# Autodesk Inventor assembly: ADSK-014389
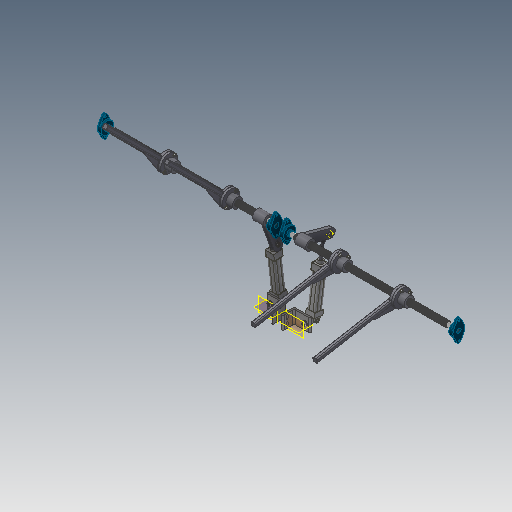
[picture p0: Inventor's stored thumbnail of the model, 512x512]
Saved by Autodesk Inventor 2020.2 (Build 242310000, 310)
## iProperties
Created: 2019-10
Part Number: ADSK-014389
Document SubType Name: Assembly
Designer: lutzd
Mass: 33938.9 g
Surface Area: 13738.5 cm^2
Volume: 4624.84 cm^3
Density: 7.3384 g/cm^3
VLDS_Profile: Default Assembly
VLDS_TimeStamp: 2016-07-29
VLDS_FailCnt: 0
VLDS_AcceptCnt: 0
Dimensions: 670,2x834,4x2050 mm
Mass: 33,939 kg
DocNumber: ADSK-014389
Folder: 01 - Themengebiete\Simplification\01 - Packaging machine\
VDS_Category: 3D Komponenten
VDS_NumSchm: Autodesk
Title: SUB-219310
Author: lutzd
Revision Number: -
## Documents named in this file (17)
- D:\07 - DEMODATEN\OTX 2019 - Dataset - UPDATE - Dez2019\Designs\07-Packing machine\ADSK-014389.iam
- D:\07 - DEMODATEN\OTX 2019 - Dataset - UPDATE - Dez2019\Designs\07-Packing machine\Parts\ADSK-011712.ipt
- D:\07 - DEMODATEN\OTX 2019 - Dataset - UPDATE - Dez2019\Designs\07-Packing machine\Parts\ADSK-011475.ipt
- D:\07 - DEMODATEN\OTX 2019 - Dataset - UPDATE - Dez2019\Designs\07-Packing machine\500598.iam
- D:\07 - DEMODATEN\OTX 2019 - Dataset - UPDATE - Dez2019\Designs\07-Packing machine\500600.iam
- D:\07 - DEMODATEN\OTX 2019 - Dataset - UPDATE - Dez2019\Content Center Files\de-DE\DIN 125-1  B\DIN 125-1 - B 8,4.ipt
- D:\07 - DEMODATEN\OTX 2019 - Dataset - UPDATE - Dez2019\Content Center Files\de-DE\ISO 4762(2)\ISO 4762 - M8 x 25ISO.ipt
- D:\07 - DEMODATEN\OTX 2019 - Dataset - UPDATE - Dez2019\Designs\07-Packing machine\500599.iam
- D:\07 - DEMODATEN\OTX 2019 - Dataset - UPDATE - Dez2019\Designs\07-Packing machine\Parts\ISO 657-2 - 100x 75x10-75.ipt
- D:\07 - DEMODATEN\OTX 2019 - Dataset - UPDATE - Dez2019\Designs\07-Packing machine\Parts\ADSK-011764.ipt
- D:\07 - DEMODATEN\OTX 2019 - Dataset - UPDATE - Dez2019\Designs\07-Packing machine\A105156.iam
- D:\07 - DEMODATEN\OTX 2019 - Dataset - UPDATE - Dez2019\Designs\07-Packing machine\A081742.iam
- D:\07 - DEMODATEN\OTX 2019 - Dataset - UPDATE - Dez2019\Content Center Files\de-DE\DIN 125-1  B\DIN 125-1 - B 10,5.ipt
- D:\07 - DEMODATEN\OTX 2019 - Dataset - UPDATE - Dez2019\Content Center Files\de-DE\ISO 4032(1)\ISO 4032 - M10DIN EN.ipt
- D:\07 - DEMODATEN\OTX 2019 - Dataset - UPDATE - Dez2019\Content Center Files\de-DE\ISO 4762(2)\ISO 4762 - M10 x 50ISO.ipt
- D:\07 - DEMODATEN\OTX 2019 - Dataset - UPDATE - Dez2019\Content Center Files\de-DE\DIN 125-1  B\DIN 125-1 - B 13.ipt
- D:\07 - DEMODATEN\OTX 2019 - Dataset - UPDATE - Dez2019\Content Center Files\de-DE\ISO 4762(2)\ISO 4762 - M12 x 25ISO.ipt
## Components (60 placed, 16 different names)
1. ADSK-011712:1 — Fluchtend:1, Passend:1, Passend:2, Passend:7, Fluchtend:10, Fluchtend:91, Fluchtend:89
2. ADSK-011712:2 — Passend:3, Passend:4, Passend:5, Passend:6, Fluchtend:8, Fluchtend:13, Fluchtend:88, Passend:90
3. ADSK-011712:3 — Passend:6, Passend:9, Passend:10, Passend:14
4. ADSK-011712:4 — Passend:7, Passend:8, Passend:11, Fluchtend:2, Fluchtend:6
5. ADSK-011475:1 — Passend:13, Fluchtend:2, Passend:16
6. ADSK-011475:2 — Passend:12, Passend:14, Passend:80, Winkel:1, Passend:83
7. 500598:1 [sub-assembly] — Passend:15, Passend:16, Passend:18, Passend:19, Passend:21, Passend:23, Passend:25, Fluchtend:3
8. 500600:1 [sub-assembly] — Passend:17, Passend:18, Passend:19, Fluchtend:6, Fluchtend:7
9. 500598:2 [sub-assembly] — Passend:46, Passend:77, Fluchtend:3, Winkel:2
10. 500600:2 [sub-assembly] — Passend:46, Fluchtend:7, Winkel:3
11. 500598:3 [sub-assembly] — Passend:78, Passend:83
12. 500600:3 [sub-assembly] — Fluchtend:8, Fluchtend:9, Winkel:4
13. 500598:4 [sub-assembly] — Passend:79, Passend:80
14. 500600:4 [sub-assembly] — Fluchtend:9
15. 500599:1 [sub-assembly] — Passend:81, Winkel:1, Passend:96, Passend:100, Passend:102, Passend:104
16. 500599:2 [sub-assembly] — Passend:82, Winkel:2, Passend:98, Passend:99, Passend:106
17. ISO 657-2 - 100x 75x10-75:1 — Fluchtend:10, Fluchtend:91, Einfügen:2, Fluchtend:90, Fluchtend:89, Fluchtend:92
18. ISO 657-2 - 100x 75x10-75:2 — Fluchtend:13, Fluchtend:88, Einfügen:1, Fluchtend:87, Passend:90, Fluchtend:92
19. ADSK-011764:1 — Einfügen:1, Fluchtend:87, Passend:91, Passend:95
20. ADSK-011764:2 — Einfügen:2, Fluchtend:90, Passend:92, Passend:94
21. A105156:1 [sub-assembly] — Passend:92, Einfügen:3, Passend:94, Passend:97
22. A105156:2 [sub-assembly] — Passend:91, Einfügen:4, Passend:95, Passend:101
23. A081742:1 [sub-assembly] — Einfügen:4, Passend:96, Passend:100, Passend:101, Passend:102
24. A081742:2 [sub-assembly] — Einfügen:3, Passend:97, Passend:98, Passend:99
25. DIN 125-1 B B 10,5:1
26. DIN 125-1 B B 10,5:2 — Passend:104
27. DIN 125-1 B B 10,5:3
28. DIN 125-1 B B 10,5:4 — Passend:106
29. DIN EN 24032 M10:1
30. DIN EN 24032 M10:2
31. ISO 4762 M10 x 50:1
32. ISO 4762 M10 x 50:2
33. DIN 125-1 B B 13:1
34. DIN 125-1 B B 13:2
35. ISO 4762 M12 x 25:1
36. ISO 4762 M12 x 25:2
37. DIN 125-1 B B 8,4:1 — Passend:21, Passend:27, Passend:29, Passend:31
38. DIN 125-1 B B 8,4:2 — Passend:23
39. DIN 125-1 B B 8,4:3 — Passend:25
40. ISO 4762 M8 x 25:1 — Passend:27
41. ISO 4762 M8 x 25:2 — Passend:29
42. ISO 4762 M8 x 25:3 — Passend:31
43. DIN 125-1 B B 8,4:4
44. DIN 125-1 B B 8,4:5
45. DIN 125-1 B B 8,4:6
46. ISO 4762 M8 x 25:4
47. ISO 4762 M8 x 25:5
48. ISO 4762 M8 x 25:6
49. DIN 125-1 B B 8,4:7
50. DIN 125-1 B B 8,4:8
51. DIN 125-1 B B 8,4:9
52. ISO 4762 M8 x 25:7
53. ISO 4762 M8 x 25:8
54. ISO 4762 M8 x 25:9
55. DIN 125-1 B B 8,4:10
56. DIN 125-1 B B 8,4:11
57. DIN 125-1 B B 8,4:12
58. ISO 4762 M8 x 25:10
59. ISO 4762 M8 x 25:11
60. ISO 4762 M8 x 25:12
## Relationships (70: Mate 47, Flush 15, Angle 4, Insert 4)
- Winkel:3 [Angle]: 500600:2
- Winkel:4 [Angle]: 500600:3
- Fluchtend:1 [Flush]: ADSK-011712:1
- Passend:1 [Mate]: ADSK-011712:1
- Passend:2 [Mate]: ADSK-011712:1
- Passend:3 [Mate]: ADSK-011712:2
- Passend:4 [Mate]: ADSK-011712:2
- Passend:5 [Mate]: ADSK-011712:2
- Passend:6 [Mate]: ADSK-011712:2 ↔ ADSK-011712:3
- Passend:7 [Mate]: ADSK-011712:1 ↔ ADSK-011712:4
- Passend:8 [Mate]: ADSK-011712:4
- Passend:9 [Mate]: ADSK-011712:3
- Passend:10 [Mate]: ADSK-011712:3
- Passend:11 [Mate]: ADSK-011712:4
- Passend:12 [Mate]: ADSK-011475:2
- Passend:13 [Mate]: ADSK-011475:1
- Passend:14 [Mate]: ADSK-011712:3 ↔ ADSK-011475:2
- Fluchtend:2 [Flush]: ADSK-011712:4 ↔ ADSK-011475:1
- Passend:15 [Mate]: 500598:1
- Passend:16 [Mate]: ADSK-011475:1 ↔ 500598:1
- Passend:17 [Mate]: 500600:1
- Passend:18 [Mate]: 500598:1 ↔ 500600:1
- Passend:19 [Mate]: 500598:1 ↔ 500600:1
- Passend:21 [Mate]: 500598:1 ↔ DIN 125-1 B B 8,4:1
- Passend:23 [Mate]: 500598:1 ↔ DIN 125-1 B B 8,4:2
- Passend:25 [Mate]: 500598:1 ↔ DIN 125-1 B B 8,4:3
- Passend:27 [Mate]: DIN 125-1 B B 8,4:1 ↔ ISO 4762 M8 x 25:1
- Passend:29 [Mate]: DIN 125-1 B B 8,4:1 ↔ ISO 4762 M8 x 25:2
- Passend:31 [Mate]: DIN 125-1 B B 8,4:1 ↔ ISO 4762 M8 x 25:3
- Passend:46 [Mate]: 500598:2 ↔ 500600:2
- Passend:77 [Mate]: 500598:2
- Passend:78 [Mate]: 500598:3
- Passend:79 [Mate]: 500598:4
- Fluchtend:3 [Flush]: 500598:1 ↔ 500598:2
- Fluchtend:6 [Flush]: ADSK-011712:4 ↔ 500600:1
- Fluchtend:7 [Flush]: 500600:1 ↔ 500600:2
- Fluchtend:8 [Flush]: ADSK-011712:2 ↔ 500600:3
- Fluchtend:9 [Flush]: 500600:3 ↔ 500600:4
- Passend:80 [Mate]: ADSK-011475:2 ↔ 500598:4
- Passend:81 [Mate]: 500599:1
- Passend:82 [Mate]: 500599:2
- Winkel:1 [Angle]: ADSK-011475:2 ↔ 500599:1
- Passend:83 [Mate]: ADSK-011475:2 ↔ 500598:3
- Winkel:2 [Angle]: 500598:2 ↔ 500599:2
- Fluchtend:10 [Flush]: ADSK-011712:1 ↔ ISO 657-2 - 100x 75x10-75:1
- Fluchtend:91 [Flush]: ADSK-011712:1 ↔ ISO 657-2 - 100x 75x10-75:1
- Fluchtend:13 [Flush]: ADSK-011712:2 ↔ ISO 657-2 - 100x 75x10-75:2
- Fluchtend:88 [Flush]: ADSK-011712:2 ↔ ISO 657-2 - 100x 75x10-75:2
- Einfügen:1 [Insert]: ISO 657-2 - 100x 75x10-75:2 ↔ ADSK-011764:1
- Einfügen:2 [Insert]: ISO 657-2 - 100x 75x10-75:1 ↔ ADSK-011764:2
- Fluchtend:87 [Flush]: ISO 657-2 - 100x 75x10-75:2 ↔ ADSK-011764:1
- Fluchtend:90 [Flush]: ISO 657-2 - 100x 75x10-75:1 ↔ ADSK-011764:2
- Fluchtend:89 [Flush]: ADSK-011712:1 ↔ ISO 657-2 - 100x 75x10-75:1
- Passend:90 [Mate]: ADSK-011712:2 ↔ ISO 657-2 - 100x 75x10-75:2
- Fluchtend:92 [Flush]: ISO 657-2 - 100x 75x10-75:1 ↔ ISO 657-2 - 100x 75x10-75:2
- Passend:91 [Mate]: ADSK-011764:1 ↔ A105156:2
- Passend:92 [Mate]: ADSK-011764:2 ↔ A105156:1
- Einfügen:3 [Insert]: A105156:1 ↔ A081742:2
- Einfügen:4 [Insert]: A105156:2 ↔ A081742:1
- Passend:94 [Mate]: ADSK-011764:2 ↔ A105156:1
- Passend:95 [Mate]: ADSK-011764:1 ↔ A105156:2
- Passend:96 [Mate]: 500599:1 ↔ A081742:1
- Passend:97 [Mate]: A105156:1 ↔ A081742:2
- Passend:98 [Mate]: 500599:2 ↔ A081742:2
- Passend:99 [Mate]: 500599:2 ↔ A081742:2
- Passend:100 [Mate]: 500599:1 ↔ A081742:1
- Passend:101 [Mate]: A105156:2 ↔ A081742:1
- Passend:102 [Mate]: 500599:1 ↔ A081742:1
- Passend:104 [Mate]: 500599:1 ↔ DIN 125-1 B B 10,5:2
- Passend:106 [Mate]: 500599:2 ↔ DIN 125-1 B B 10,5:4
## Named parameters: d33_d19 = 0, d34_d20 = 0, d35_d21 = 0, d36_d22 = 0, d37_d23 = 0, d38_d24 = 0, d39_d25 = 0, d40_d26 = 0, d41_d27 = 0, d42_d28 = 0, d43_d29 = 0, d44_d30 = 0, d45_d31 = 0, d46_d32 = 0, d76_d33_d19 = 0, d77_d34_d20 = 0, d78_d35_d21 = 0, d79_d36_d22 = 0, d80_d37_d23 = 0, d81_d38_d24 = 0, d82_d39_d25 = 0, d83_d40_d26 = 0, d84_d41_d27 = 0, d85_d42_d28 = 0, d86_d43_d29 = 0, d87_d44_d30 = 0, d88_d45_d31 = 0, d89_d46_d32 = 0, d90_d75 = 0, d91_d33_d19 = 0, d92_d34_d20 = 0, d93_d35_d21 = 0, d94_d36_d22 = 0, d95_d37_d23 = 0, d96_d38_d24 = 0, d97_d39_d25 = 0, d98_d40_d26 = 0, d99_d41_d27 = 0, d100_d42_d28 = 0, d101_d43_d29 = 0, d102_d44_d30 = 0, d103_d45_d31 = 0, d104_d46_d32 = 0, d105_d75 = 0
